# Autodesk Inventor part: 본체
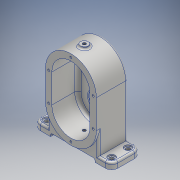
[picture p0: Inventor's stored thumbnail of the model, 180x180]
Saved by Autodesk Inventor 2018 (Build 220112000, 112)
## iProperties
Created: 2021-05
Part Number: 본체
Material: 알루미늄 6061
Document SubType Name: Modeling
Designer: Admin
Density: 2.7 g/cm^3
Appearance: 알루미늄 - 평지
Mass: 756.242 g
Surface Area: 582.886 cm^2
Volume: 280.09 cm^3
Author: Admin
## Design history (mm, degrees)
sketch "스케치1"
  geometry: L1 (0, -87.5)-(0, 87.5) reference; L2 (56, 0)-(-56, 0) reference; L3 (0, 22.5)-(0, -22.5); L4 (-40, 22.5)-(-40, -22.5); L5 (40, -22.5)-(40, 22.5); A1 r 40 centre (0, 22.5) between (40, 22.5) and (-40, 22.5); A2 r 40 centre (0, -22.5) between (-40, -22.5) and (40, -22.5); 1 further point
  constraints: 8 end point, 4 point on circle, 4 tangent, 2 centre point, 2 point on line, 1 midpoint, 1 parallel, 1 symmetric about line
  dimensions: "d5" = 80 distance between parallel lines of L4 L5; "d6" = 45 distance of L3.start L3.end
extrude "돌출1" new body sketch "스케치1" stored distance "d3" = 49; taper "d4" = 0 deg
node "작업 평면1"
sketch "스케치2"
  geometry: L1 (40, 24.5)-(40, -24.5) reference; L2 (-40, 24.5)-(40, 24.5) reference; L3 (-40, -24.5)-(-40, 24.5) reference; L4 (40, -24.5)-(-40, -24.5) reference; L5 (0, -34.3)-(0, 34.3) reference; L6 (-85.4, 0)-(85.4, 0) reference; L7 (-61, 24.5)-(61, 24.5); L8 (61, 24.5)-(61, -21.5); L9 (61, -21.5)-(-61, -21.5); L10 (-61, -21.5)-(-61, 24.5); 2 further points
  constraints: 8 end point, 2 midpoint, 2 parallel, 1 horizontal, 1 perpendicular, 1 other
  dimensions: "d8" = 122 distance of L8.end L9.end; "d9" = 46 distance of L7.end L8.end
extrude "돌출2" join sketch "스케치2" distance "d10" = 10; taper "d11" = 0 deg
sketch "스케치3"
  geometry: L1 (-24.4, 69.5)-(146.4, 69.5) reference; L2 (61, -26.4)-(61, 158.4) reference; L3 (101, 47)-(101, 92) reference; L4 (21, 92)-(21, 47) reference; L5 (0, 10)-(45.801, 10) reference; L6 (0, 0)-(0, 10) reference; L7 (122, 0)-(0, 0) reference; L8 (122, 0)-(122, 10) reference; L9 (76.199, 10)-(122, 10) reference; L10 (26, 5)-(96, 5); L11 (96, 5)-(96, 0); L12 (96, 0)-(26, 0); L13 (26, 0)-(26, 5); L14 (26, 5)-(96, 0); L15 (96, 5)-(26, 0); A1 r 40 centre (61, 92) between (101, 92) and (21, 92) reference; A2 r 40 centre (61, 47) between (21, 47) and (101, 47) reference; A3 r 40 centre (61, 47) between (45.801, 10) and (76.199, 10) reference; 3 further points
  constraints: 12 end point, 4 midpoint, 2 parallel, 1 horizontal, 1 perpendicular, 1 point on line
  dimensions: "d12" = 70 distance of L11.end L12.end; "d13" = 5 distance between parallel lines of L7 L10
extrude "돌출3" cut sketch "스케치3" stored distance "d14" = 10; taper "d15" = 0 deg
sketch "스케치4"
  geometry: L1 (35, 24.5)-(-35, 24.5) reference; L2 (35, -21.5)-(35, 24.5) reference; L3 (-35, -21.5)-(35, -21.5) reference; L4 (-35, -21.5)-(-35, 24.5) reference; L5 (-35, 24.5)-(-35, -21.5) reference; L6 (-35, -21.5)-(-61, -21.5) reference; L7 (-61, -21.5)-(-61, 24.5) reference; L8 (-61, 24.5)-(-35, 24.5) reference; L9 (35, -21.5)-(35, 24.5) reference; L10 (35, 24.5)-(61, 24.5) reference; L11 (61, 24.5)-(61, -21.5) reference; L12 (61, -21.5)-(35, -21.5) reference; L13 (-85.4, 0)-(85.4, 0) reference; L14 (0, -34.3)-(0, 34.3) reference; L15 (-35, -21.5)-(-35, 24.5) reference; L16 (61, -21.5)-(35, -21.5) reference; L17 (40, 24.5)-(40, -24.5) reference; L18 (-40, 24.5)-(40, 24.5) reference; L19 (-40, -24.5)-(-40, 24.5) reference; L20 (40, -24.5)-(-40, -24.5) reference; L21 (-40, 24.5)-(40, 24.5); L22 (40, 24.5)-(40, -21.5); L23 (40, -21.5)-(-40, -21.5); L24 (-40, -21.5)-(-40, 24.5); 1 further point
  constraints: 8 end point, 2 parallel, 2 point on line, 1 horizontal, 1 perpendicular
extrude "돌출4" join sketch "스케치4" stored distance "d16" = 10; taper "d17" = 0 deg
sketch "스케치5"
  geometry: L1 (61, -59.5)-(40, -59.5) reference; L2 (61, -69.5)-(61, -59.5) reference; L3 (35, -69.5)-(61, -69.5) reference; L4 (35, -69.5)-(35, -64.5) reference; L5 (35, -64.5)-(-35, -64.5) reference; L6 (-35, -64.5)-(-35, -69.5) reference; L7 (-61, -69.5)-(-35, -69.5) reference; L8 (-61, -69.5)-(-61, -59.5) reference; L9 (-40, -59.5)-(-61, -59.5) reference; L10 (-40, -59.5)-(-40, 22.5) reference; L11 (40, 22.5)-(40, -59.5) reference; L12 (-85.4, 0)-(85.4, 0) reference; L13 (0, -95.9)-(0, 88.9) reference; L14 (0, 22.5)-(0, -22.5); L15 (-30, 22.5)-(-30, -22.5); L16 (30, -22.5)-(30, 22.5); A1 r 40 centre (0, 22.5) between (40, 22.5) and (-40, 22.5) reference; A2 r 30 centre (0, 22.5) between (30, 22.5) and (-30, 22.5); A3 r 30 centre (0, -22.5) between (-30, -22.5) and (30, -22.5); 2 further points
  constraints: 8 end point, 4 point on circle, 4 tangent, 2 centre point, 2 point on line, 1 midpoint, 1 parallel, 1 other
  dimensions: "d18" = 30 radius of A2; "d19" = 45 distance of L14.end L14.start
extrude "돌출5" cut sketch "스케치5" distance "d20" = 41; taper "d21" = 0 deg
sketch "스케치6"
  geometry: L1 (-85.4, 0)-(85.4, 0) reference; L2 (0, 95.9)-(0, -88.9) reference; L3 (61, 59.5)-(40, 59.5) reference; L4 (61, 69.5)-(61, 59.5) reference; L5 (35, 69.5)-(61, 69.5) reference; L6 (35, 69.5)-(35, 64.5) reference; L7 (35, 64.5)-(-35, 64.5) reference; L8 (-35, 64.5)-(-35, 69.5) reference; L9 (-61, 69.5)-(-35, 69.5) reference; L10 (-61, 69.5)-(-61, 59.5) reference; L11 (-40, 59.5)-(-61, 59.5) reference; L12 (-40, 59.5)-(-40, -22.5) reference; L13 (40, -22.5)-(40, 59.5) reference; L14 (0, -22.5)-(0, 22.5); L15 (26, -22.5)-(26, 22.5); L16 (-26, 22.5)-(-26, -22.5); A1 r 40 centre (0, -22.5) between (-40, -22.5) and (40, -22.5) reference; A2 r 26 centre (0, -22.5) between (-26, -22.5) and (26, -22.5); A3 r 26 centre (0, 22.5) between (26, 22.5) and (-26, 22.5); 2 further points
  constraints: 8 end point, 4 point on circle, 4 tangent, 2 centre point, 2 point on line, 1 midpoint, 1 parallel, 1 other
  dimensions: "d22" = 52 distance between parallel lines of L16 L15; "d23" = 45 distance of L14.end L14.start
extrude "돌출6" join sketch "스케치6" distance "d24" = 8; taper "d25" = 0 deg
sketch "스케치7"
  geometry: L1 (-26, -22.5)-(-26, 22.5) reference; L2 (26, 22.5)-(26, -22.5) reference; L3 (-85.4, 0)-(85.4, 0) reference; L4 (0, 95.9)-(0, -88.9) reference; L5 (0, -22.5)-(0, 22.5); L6 (26, 7.5)-(26, 22.5); L7 (-26, 22.5)-(-26, 7.5); L8 (26, 7.5)-(-26, 7.5); A1 r 26 centre (0, -22.5) between (-26, -22.5) and (26, -22.5) reference; A2 r 26 centre (0, 22.5) between (26, 22.5) and (-26, 22.5) reference; A3 r 26 centre (0, 22.5) between (26, 22.5) and (-26, 22.5); 2 further points
  constraints: 10 end point, 2 point on circle, 2 tangent, 1 centre point, 1 collinear, 1 concentric, 1 midpoint, 1 parallel, 1 perpendicular
  dimensions: "d26" = 30 distance from line of L8 L5.start; "d27" = 15 distance of L7.end L1.end
extrude "돌출7" join sketch "스케치7" distance "d28" = 3; taper "d29" = 0 deg
sketch "스케치8"
  geometry: L1 (-26, 22.5)-(-26, -22.5) reference; L2 (26, -22.5)-(26, 22.5) reference; L3 (61, -59.5)-(40, -59.5) reference; L4 (61, -69.5)-(61, -59.5) reference; L5 (35, -69.5)-(61, -69.5) reference; L6 (35, -69.5)-(35, -64.5) reference; L7 (35, -64.5)-(-35, -64.5) reference; L8 (-35, -64.5)-(-35, -69.5) reference; L9 (-61, -69.5)-(-35, -69.5) reference; L10 (-61, -69.5)-(-61, -59.5) reference; L11 (-40, -59.5)-(-61, -59.5) reference; L12 (-40, -59.5)-(-40, 22.5) reference; L13 (40, 22.5)-(40, -59.5) reference; L14 (-85.4, 0)-(85.4, 0) reference; L15 (0, -95.9)-(0, 88.9) reference; C1 r 14 at (0, 22.5); C2 r 14 at (0, -22.5); A1 r 26 centre (0, 22.5) between (26, 22.5) and (-26, 22.5) reference; A2 r 26 centre (0, -22.5) between (-26, -22.5) and (26, -22.5) reference; A3 r 40 centre (0, 22.5) between (40, 22.5) and (-40, 22.5) reference; 1 further point
  constraints: 2 centre point, 2 coincident
  dimensions: "d30" = 28 diameter of C1; "d31" = 28 diameter of C2
extrude "돌출8" cut sketch "스케치8" distance "d32" = 8; taper "d33" = 0 deg
sketch "스케치9"
  geometry: L1 (-30, -45)-(-30, 0) reference; L2 (30, 0)-(30, -45) reference; L3 (-85.4, -22.5)-(85.4, -22.5) reference; L4 (0, -118.4)-(0, 66.4) reference; C1 r 14 at (0, 0) reference; C2 r 14 at (0, 0) reference; C3 r 14 at (0, -45) reference; C4 r 11 at (0, 0); C5 r 10 at (0, -45); A1 r 30 centre (0, -45) between (-30, -45) and (30, -45) reference; A2 r 30 centre (0, 0) between (30, 0) and (-30, 0) reference; 1 further point
  constraints: 2 centre point, 2 coincident
  dimensions: "d34" = 22 diameter of C4; "d35" = 20 diameter of C5
extrude "돌출9" cut sketch "스케치9" distance "d36" = 4; taper "d37" = 0 deg
sketch "스케치10"
  geometry: L1 (-30, -45)-(-30, 0) reference; L2 (30, 0)-(30, -45) reference; C1 r 14 at (0, 0) reference; C2 r 14 at (0, -45) reference; C3 r 14 at (0, 0); A1 r 30 centre (0, -45) between (-30, -45) and (30, -45) reference; A2 r 30 centre (0, 0) between (30, 0) and (-30, 0) reference; 1 further point
  constraints: 1 centre point, 1 coincident
  dimensions: "d38" = 28 diameter of C3
  node "투영된 루프13"
extrude "돌출10" cut sketch "스케치10" distance "d39" = 4; taper "d40" = 0 deg
sketch "스케치12"
  geometry: L1 (-30, -22.5)-(-30, 22.5) reference; L2 (30, 22.5)-(30, -22.5) reference; L3 (40, -22.5)-(40, 22.5) reference; L4 (-40, 22.5)-(-40, -22.5) reference; L5 (-85.4, 0)-(85.4, 0) reference; L6 (0, -95.9)-(0, 88.9) reference; L7 (0, 22.5)-(0, -22.5); L8 (-35, 22.5)-(-35, -22.5); L9 (35, -22.5)-(35, 22.5); A1 r 30 centre (0, -22.5) between (-30, -22.5) and (30, -22.5) reference; A2 r 30 centre (0, 22.5) between (30, 22.5) and (-30, 22.5) reference; A3 r 40 centre (0, 22.5) between (40, 22.5) and (-40, 22.5) reference; A4 r 40 centre (0, -22.5) between (-40, -22.5) and (40, -22.5) reference; A5 r 35 centre (0, 22.5) between (35, 22.5) and (-35, 22.5); A6 r 35 centre (0, -22.5) between (-35, -22.5) and (35, -22.5); 8 further points
  constraints: 8 end point, 6 point on circle, 4 coincident, 4 tangent, 2 centre point, 1 collinear, 1 midpoint, 1 parallel
  dimensions: "d42" = 35 radius of A5
hole "구멍1" sketch "스케치12" at (-35, 22.5), (-35, -22.5), (35, -22.5), (0, -57.5), (0, 57.5), (35, 22.5) diameter "d43" = 3.242; stored, may be unused: countersink angle "d47" = 90 deg, drill point angle "d49" = 118 deg; dims "d44" = 8, "d45" = 4, "d46" = 2, "d48" = 10
sketch "스케치13"
  geometry: L1 (0, 95.9)-(0, -88.9) reference; L2 (-85.4, 0)-(85.4, 0) reference; L3 (0, -22.5)-(-54.532, 8.984); L4 (0, -22.5)-(52.341, 7.719); C1 r 14 at (0, -22.5) reference; A1 r 26 centre (0, -22.5) between (-26, -22.5) and (26, -22.5) reference; A2 r 20 centre (0, -22.5) between (0, -42.5) and (17.321, -12.5); 2 further points
  constraints: 4 end point, 3 point on circle, 3 point on line, 1 centre point, 1 coincident
  dimensions: "d50" = 120 deg angle of L3 L1; "d51" = 120 deg angle of L1 L4; "d52" = 40 diameter of A2
hole "구멍2" sketch "스케치13" at (0, -42.5), (17.321, -12.5), (-17.321, -12.5) diameter "d53" = 3.242; stored, may be unused: countersink angle "d57" = 90 deg, drill point angle "d59" = 118 deg; dims "d54" = 8, "d55" = 4, "d56" = 2, "d58" = 10
sketch "스케치14"
  geometry: L1 (-5, 0)-(75, 0) reference; L2 (-5, -3)-(75, -3) reference; L3 (35, -15)-(35, 69) reference; C1 r 6 at (35, 18); 1 further point
  constraints: 1 centre point, 1 point on line
  dimensions: "d60" = 12 diameter of C1; "d62" = 21 distance from line of L2 C1.centre
extrude "돌출11" cut sketch "스케치14" distance "d63" = 1; taper "d64" = 0 deg
sketch "스케치15"
  geometry: C1 r 6 at (0, 0) reference; 2 further points
  constraints: 1 coincident
hole "구멍3" sketch "스케치15" at (0, 0) diameter "d65" = 4.917; stored, may be unused: countersink angle "d69" = 90 deg, drill point angle "d71" = 118 deg; dims "d66" = 12, "d67" = 4, "d68" = 2, "d70" = 17.1
node "작업 평면4"
  node "작업 평면3"
sketch "스케치16"
  geometry: L1 (-40, -24.5)-(40, -24.5) reference; C1 r 6 at (0, -3.5)
  constraints: 1 centre point
  dimensions: "d73" = 12 diameter of C1; "d100" = 21 distance from line of C1.centre L1
extrude "돌출12" join sketch "스케치16" stored distance "d74" = 1; taper "d75" = 0 deg
sketch "스케치17"
  geometry: C1 r 6 at (0, 0) reference; 2 further points
  constraints: 1 coincident
hole "구멍4" sketch "스케치17" at (0, 0) diameter "d76" = 4.917; stored, may be unused: countersink angle "d80" = 90 deg, drill point angle "d82" = 118 deg; dims "d77" = 12, "d78" = 4, "d79" = 2, "d81" = 17.1
fillet "모깎기1" dims "d83" = 10
sketch "스케치18"
  geometry: L1 (-51, 24.5)-(-35, 24.5) reference; L2 (-35, 24.5)-(-35, -21.5) reference; L3 (-35, -21.5)-(-51, -21.5) reference; L4 (-61, -11.5)-(-61, 14.5) reference; L5 (61, 14.5)-(61, -11.5) reference; L6 (51, -21.5)-(35, -21.5) reference; L7 (35, -21.5)-(35, 24.5) reference; L8 (35, 24.5)-(51, 24.5) reference; A1 r 10 centre (-51, 14.5) between (-51, 24.5) and (-61, 14.5) reference; A2 r 10 centre (-51, -11.5) between (-61, -11.5) and (-51, -21.5) reference; A3 r 10 centre (51, 14.5) between (61, 14.5) and (51, 24.5) reference; A4 r 10 centre (51, -11.5) between (51, -21.5) and (61, -11.5) reference; 5 further points
  constraints: 4 coincident
hole "구멍5" sketch "스케치18" at (-51, 14.5), (-51, -11.5), (51, -11.5), (51, 14.5) diameter "d84" = 6.6; stored, may be unused: countersink angle "d88" = 90 deg, drill point angle "d90" = 118 deg; dims "d85" = 12, "d86" = 11, "d87" = 2, "d89" = 17.1
fillet "모깎기2" dims "d91" = 0.3, "d92" = 5, "d93" = 3
chamfer "모따기1" distance "d94" = 1; stored, may be unused: second distance "d95" = 2, angle "d96" = 45 deg
sketch "스케치19"
  geometry: L1 (35, 69.5)-(51, 69.5) reference; 2 further points
  constraints: 1 other
  dimensions: "d97" = 12 distance from line of L1 point (-0.138, 57.5)
feature "엠보싱1" sketch "스케치19" dims "d98" = 0.5, "d99" = 0
node "솔리드1"
node "투영된 루프1"
node "투영된 루프2"
node "투영된 루프3"
node "투영된 루프4"
node "투영된 루프5"
node "투영된 루프6"
node "투영된 루프7"
node "투영된 루프8"
node "투영된 루프9"
node "투영된 루프10"
node "투영된 루프11"
node "투영된 루프12"
node "투영된 루프14"
node "투영된 루프15"
node "투영된 루프16"
node "투영된 루프17"
other parameters: "d1" = 135, "d7" = -69.5, "d72" = 3
